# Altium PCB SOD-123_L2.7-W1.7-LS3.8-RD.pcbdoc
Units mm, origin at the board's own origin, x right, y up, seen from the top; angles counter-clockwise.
Board outline 16.92 x 14.7 mm, 2 copper layers (Top Layer, Bottom Layer), stack 0 mm thick; 1 components, 0 nets, 2 pads, 0 vias.
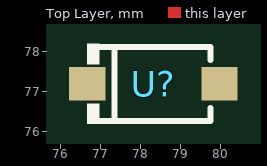
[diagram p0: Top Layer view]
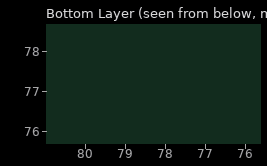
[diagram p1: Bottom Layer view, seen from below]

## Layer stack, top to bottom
Top Layer: signal copper (thickness not stored)
Bottom Layer: signal copper (thickness not stored)

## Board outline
86.77,69.85 69.85,69.85 69.85,84.555 86.77,84.555

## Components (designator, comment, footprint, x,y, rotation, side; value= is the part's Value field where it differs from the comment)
U? "" SOD-123_L2.7-W1.7-LS3.8-RD 78.31,77.202 r0 top

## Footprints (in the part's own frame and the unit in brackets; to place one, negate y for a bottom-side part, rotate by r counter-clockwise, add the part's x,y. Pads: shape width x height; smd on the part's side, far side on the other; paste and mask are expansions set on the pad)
SOD-123_L2.7-W1.7-LS3.8-RD [mm]
  rect 0.91x0.84 smd: 1(-1.655,0) 2(1.655,0)
  silkscreen extent -1.65,-1 1.43,1

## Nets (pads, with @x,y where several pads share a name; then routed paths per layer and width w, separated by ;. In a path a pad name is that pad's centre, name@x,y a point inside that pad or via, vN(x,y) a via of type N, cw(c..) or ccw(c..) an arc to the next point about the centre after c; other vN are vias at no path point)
pads on no net: U?.1 U?.2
